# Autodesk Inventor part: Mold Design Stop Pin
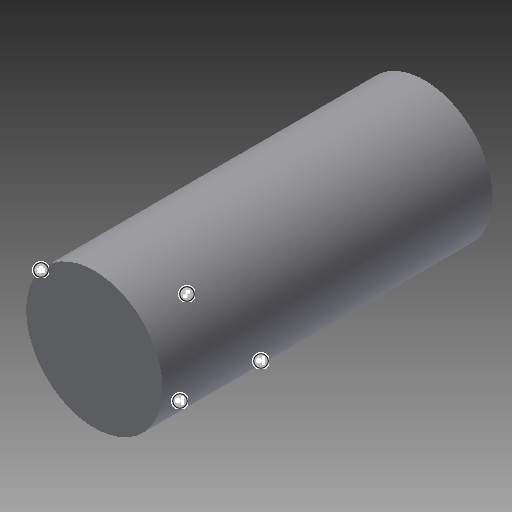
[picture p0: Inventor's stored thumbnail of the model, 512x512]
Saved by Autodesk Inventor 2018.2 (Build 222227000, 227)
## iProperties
Created: 2007-09
Part Number: Mold Design Stop Pin
Document SubType Name: Modeling
Designer: mxwang
Density: 1 g/cm^3
Material: Generic
Appearance: Default
Author: mxwang
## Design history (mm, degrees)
sketch "Sketch1"
  geometry: C1 r 4.132 at (0, 0); 1 further point
  constraints: 1 centre point, 1 coincident
  dimensions: "Diameter" = 8.26421 diameter of C1
extrude "Extrusion1" new body sketch "Sketch1" taper "d2" = 0 deg; stored distance "Height" = 20
body "Solid1"
other parameters: "d3" = 0, "d4" = 0, "d9" = 0, "d10" = 0
